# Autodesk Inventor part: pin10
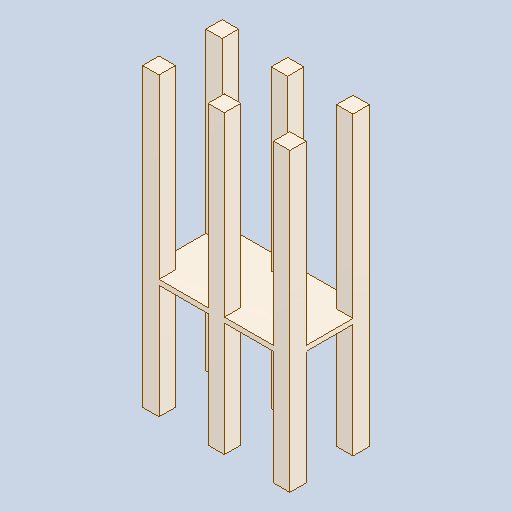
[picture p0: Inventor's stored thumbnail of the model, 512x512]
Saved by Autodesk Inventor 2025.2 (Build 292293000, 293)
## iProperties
Created: 2025-04
Part Number: pin10
Material: Generic
Description: PART--DESC
Document SubType Name: Modeling
Designer: BennF
Density: 1 g/cm^3
Appearance: Default
Author: BennF
Revision Number: NONE
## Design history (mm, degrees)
feature "Solid"
body "Solid1"
